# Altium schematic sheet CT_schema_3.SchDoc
size 307 x 173 mm
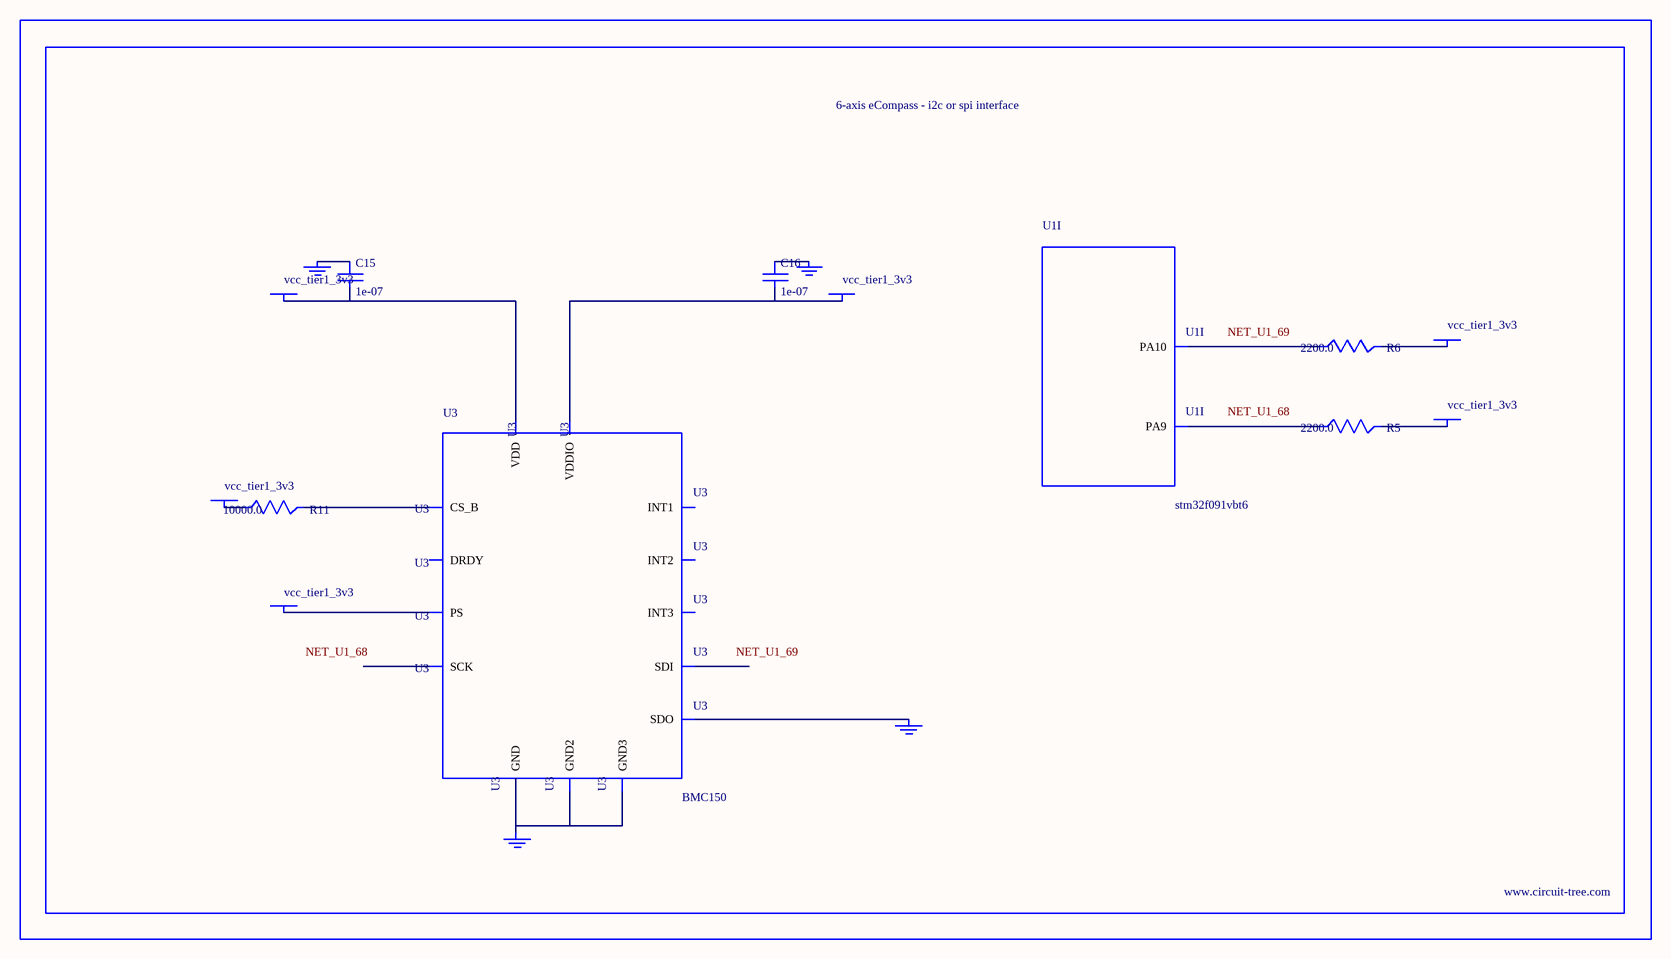
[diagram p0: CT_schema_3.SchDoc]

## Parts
BORDER2  (no value)
C15  1e-07  [C0402]
C16  1e-07  [C0402]
GND_INSTANCE_2_0  (no value)
GND_INSTANCE_2_1  (no value)
GND_INSTANCE_2_2  (no value)
GND_INSTANCE_2_3  (no value)
POWER_INSTANCE_2_0  vcc_tier1_3v3
POWER_INSTANCE_2_1  vcc_tier1_3v3
POWER_INSTANCE_2_2  vcc_tier1_3v3
POWER_INSTANCE_2_3  vcc_tier1_3v3
POWER_INSTANCE_2_4  vcc_tier1_3v3
POWER_INSTANCE_2_5  vcc_tier1_3v3
R5  2200.0  [R0603]
R6  2200.0  [R0603]
R11  10000.0  [R0603]
U1  stm32f091vbt6  [LQFP100]  (part I of 10)
U3  BMC150  [LGA14R35P5X6_200X200X100]

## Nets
NetC15_1: C15.1 GND_INSTANCE_2_1.0(GND)
NetC15_2: C15.2 POWER_INSTANCE_2_0.0(PWR) U3.8(VDD)
NetC16_1: C16.1 GND_INSTANCE_2_2.0(GND)
NetC16_2: C16.2 POWER_INSTANCE_2_1.0(PWR) U3.10(VDDIO)
NetGND_INSTANCE_2_0_0: GND_INSTANCE_2_0.0(GND) U3.1(SDO)
NetGND_INSTANCE_2_3_0: GND_INSTANCE_2_3.0(GND) U3.6(GND) U3.7(GND2) U3.9(GND3)
NetPOWER_INSTANCE_2_2_0: POWER_INSTANCE_2_2.0(PWR) R11.1
NetPOWER_INSTANCE_2_3_0: POWER_INSTANCE_2_3.0(PWR) U3.13(PS)
NetPOWER_INSTANCE_2_4_0: POWER_INSTANCE_2_4.0(PWR) R5.2
NetPOWER_INSTANCE_2_5_0: POWER_INSTANCE_2_5.0(PWR) R6.2
NetR5_1: R5.1 U1.68(PA9)
NetR6_1: R6.1 U1.69(PA10)
NetR11_2: R11.2 U3.12(CS_B)

Not connected (* = marked no-connect by the designer): U3 2(INT1) 3(INT2) 4(DRDY) 5(INT3) 11(SCK) 14(SDI)

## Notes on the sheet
- Labels drawn without touching a wire or pin: NET_U1_68, NET_U1_69

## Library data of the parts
BORDER2 = BORDER_PAGE2
C15 C16 = C0402C104K3RACTU
GND_INSTANCE_2_0-GND_INSTANCE_2_3 = GND
POWER_INSTANCE_2_0-POWER_INSTANCE_2_5 = PWR
R5 R6 = RC0603JR-072K2L
R11 = RC0603JR-0710KL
